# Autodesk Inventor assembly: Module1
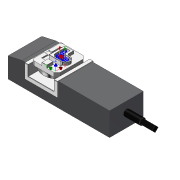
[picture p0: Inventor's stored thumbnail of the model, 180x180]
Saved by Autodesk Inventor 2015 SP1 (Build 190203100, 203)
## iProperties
Created: 2015-06
Part Number: Module1
Document SubType Name: Assembly
Designer: suporte
Author: suporte
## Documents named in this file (3)
- C:\Users\suporte\Desktop\#07- CNC Milling\#07- CNC Milling_M1\#07- CNC Milling_M1.iam
- C:\Users\suporte\Desktop\#07- CNC Milling\#07- CNC Milling_M1\#07- CNC Milling_M1.ipt
- C:\Users\suporte\Desktop\#07- CNC Milling\#07- CNC Milling_M1\Small Clamp.ipt
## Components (2 placed, 2 different names)
1. #07- CNC Milling_M1:1 — Mate:1, Flush:1, Flush:2
2. Small Clamp:1 — Mate:1, Flush:1, Flush:2
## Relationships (3: Flush 2, Mate 1)
- Mate:1: #07- CNC Milling_M1:1 ↔ Small Clamp:1
- Flush:1: #07- CNC Milling_M1:1 ↔ Small Clamp:1
- Flush:2: #07- CNC Milling_M1:1 ↔ Small Clamp:1
